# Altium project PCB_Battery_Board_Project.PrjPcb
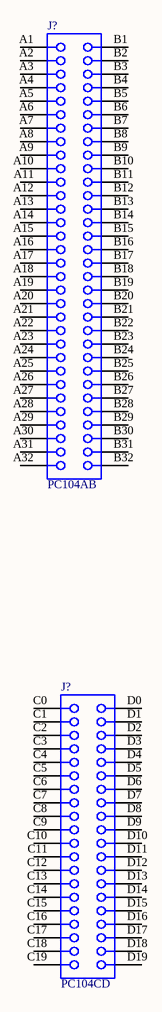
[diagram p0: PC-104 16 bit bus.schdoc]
1 sheet, 2 parts. Net scope: global (net labels, ports and power ports of the same name join across sheets).
Board files: PC-104 16 bit bus.PCBDOC, Battery-Board.PcbDoc

## Sheet PC-104 16 bit bus.schdoc: PC-104 16 bit bus
size B; Organization: Organization; Address1: Address1; Address2: Address2; Address3: Address3; Address4: Address4; DocumentNumber: 1; Revision: 0; SheetNumber: 2; SheetTotal: 2

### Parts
(Parts that share a designator on the sheet are numbered #1, #2 ... from top to bottom, then left to right.)
J?#1  PC104AB  [PC104AB]
J?#2  PC104CD  [PC104CD]

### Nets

Not connected (* = marked no-connect by the designer): J?#1 A1 A2 A3 A4 A5 A6 A7 A8 A9 A10 A11 A12 A13 A14 A15 A16 A17 A18 A19 A20 A21 A22 A23 A24 A25 A26 A27 A28 A29 A30 A31 A32 B1 B2 B3 B4 B5 B6 B7 B8 B9 B10 B11 B12 B13 B14 B15 B16 B17 B18 B19 B20 B21 B22 B23 B24 B25 B26 B27 B28 B29 B30 B31 B32; J?#2 C0 C1 C2 C3 C4 C5 C6 C7 C8 C9 C10 C11 C12 C13 C14 C15 C16 C17 C18 C19 D0 D1 D2 D3 D4 D5 D6 D7 D8 D9 D10 D11 D12 D13 D14 D15 D16 D17 D18 D19

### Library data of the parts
J?#1 = PC104AB: 64-Pin Connector; Text Field6: Alternate Layout Available; Text Field7: Published 14-Feb-2002
J?#2 = PC104CD: 40-Pin Connector; Text Field6: Alternate Layout Available; Text Field7: Published 14-Feb-2002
